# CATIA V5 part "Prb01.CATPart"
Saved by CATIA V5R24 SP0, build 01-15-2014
Part number: Part2
Bounding box of the stored display mesh (mm): x -83 to 0, y -70.837 to 70.837, z -70.764 to 70.764
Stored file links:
  C:\Users\cdl\Downloads\2024_CAD_midterm\Prb02.CATPart
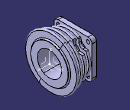
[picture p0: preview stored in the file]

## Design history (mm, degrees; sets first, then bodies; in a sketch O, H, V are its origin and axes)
AxisSystem1: origin (0, 0, 0), X (1, 0, 0), Y (0, 1, 0), Z (0, 0, 1)
Body1 (main body)
  Sketch1 on zx-plane, origin (0, 0, 0), H (-1, 0, 0), V (0, 0, 1)
    construction line L1 (0, 0) -> (74, 0)
    construction line L2 (7, 0) -> (7, 68)
    point P2 (7, 0)
    construction line L3 (22, 0) -> (22, 64)
    point P4 (22, 0)
    construction line L4 (37, 0) -> (37, 60)
    point P6 (37, 0)
    axis line L5 (52, 0) -> (52, 56)
    point P8 (52, 0)
    arc A1 centre (7, 68) radius 3 from (9.9995, 68.0524) to (4.0005, 68.0523) ccw
    arc A2 centre (22, 64) radius 3 from (24.9995, 64.0524) to (19.0005, 64.0523) ccw
    arc A3 centre (37, 60) radius 3 from (39.9995, 60.0524) to (34.0005, 60.0523) ccw
    arc A4 centre (52, 56) radius 3 from (54.9995, 56.0523) to (49.0005, 56.0523) ccw
    line L6 (4.0005, 68.0524) -> (2.8126, 0)
    point P10 (4.0005, 68.0524)
    point P11 (2.8126, 0)
    line L7 (9.9995, 68.0524) -> (11.1874, 0)
    point P13 (11.1874, 0)
    line L8 (19.0005, 64.0524) -> (17.8824, 0)
    point P14 (19.0005, 64.0524)
    point P15 (17.8824, 0)
    line L9 (24.9995, 64.0524) -> (26.1176, 0)
    point P17 (26.1176, 0)
    line L10 (34.0005, 60.0524) -> (32.9522, 0)
    point P18 (34.0005, 60.0524)
    point P19 (32.9522, 0)
    line L11 (39.9995, 60.0524) -> (41.0478, 0)
    point P21 (41.0478, 0)
    line L12 (49.0005, 56.0524) -> (48.0221, 0)
    point P22 (49.0005, 56.0524)
    point P23 (48.0221, 0)
    line L13 (54.9995, 56.0523) -> (55.9779, 0)
    point P25 (55.9779, 0)
    point P26 (4.0005, 68.0523)
    point P27 (19.0005, 64.0523)
    point P28 (34.0005, 60.0523)
    point P29 (49.0005, 56.0523)
    line L14 (2.8126, 0) -> (11.1874, 0)
    line L15 (17.8824, 0) -> (26.1176, 0)
    line L16 (32.9522, 0) -> (41.0478, 0)
    line L17 (48.0221, 0) -> (55.9779, 0)
    distance V L2 = 7
    length L2 = 68
    length L3 = 64
    length L4 = 60
    length L5 = 56
    distance L2 L3 = 15
    distance L3 L4 = 15
    distance L4 L5 = 15
    radius A1 = 3
    radius A2 = 3
    radius A3 = 3
    radius A4 = 3
    angle L6 L7 = 2
    angle L8 L9 = 2
    angle L10 L11 = 2
    angle L12 L13 = 2
    horizontal: L1 H, L14 H, L15 H, L16 H, L17 H
    coincidence: P2 L1, P4 L1, P8 L1, A1 P10, L1 P11, L1 P13, A2 P14, L1 P15, L1 P17, A3 P18, L1 P19, L1 P21, A4 P22, L1 P23, L1 P25, L6 P26, L8 P27, L10 P28, L12 P29
    vertical: L2 V, L3 V, L4 V, L5 V
    midpoint: P6 L1
    tangency: L6 A1, L7 A1, L8 A2, L9 A2, L10 A3, L11 A3, L12 A4, L13 A4
    symmetry: L6 L7 L2, L8 L9 L3, L10 L11 L4, L12 L13 L5
  Shaft1: profile Sketch1, axis Sketch1.H, angle 360
  Sketch2 on zx-plane, origin (0, 0, 0), H (-1, 0, 0), V (0, 0, 1)
    point P1 (7, 0)
    line L1 (7, 0) -> (63, 0)
    line L2 (63, 0) -> (63, 40)
    line L3 (63, 40) -> (7, 40)
    line L4 (7, 40) -> (7, 0)
    distance L4 V = 7
    length L2 = 40
    length L1 = 56
    coincidence: P1 H
    horizontal: L1 H, L3 H
    vertical: L2 V, L4 V
  Shaft2: profile Sketch2, axis axis of face of Shaft1 from Sketch1.L6, angle 360
  Sketch3 on face of Shaft2 from Sketch2.L2, origin (-63, 0, 0), H (0, -1, 0), V (0, 0, 1)
    line L1 (51, 51) -> (51, -51)
    line L2 (51, -51) -> (-51, -51)
    line L3 (-51, -51) -> (-51, 51)
    line L4 (-51, 51) -> (51, 51)
    length L3 = 102
    length L4 = 102
    vertical: L1 V, L3 V
    horizontal: L2 H, L4 H
    equidistance: L1 L3 O, L2 L4 O
  Pad1: profile Sketch3, direction (-1, 0, 0), length 12
  Sketch4 on end face of Pad1, origin (-75, 0, 0), H (0, -1, 0), V (0, 0, 1)
    circle A1 centre (0, 0) radius 39
    radius A1 = 39
  Pad2: profile Sketch4, direction (-1, 0, 0), length 8
  Fillet1: radius 11, on edge [face of Pad1 from Sketch3.L2 | face of Pad1 from Sketch3.L3]; edge [face of Pad1 from Sketch3.L3 | face of Pad1 from Sketch3.L4]; edge [face of Pad1 from Sketch3.L1 | face of Pad1 from Sketch3.L2]; edge [face of Pad1 from Sketch3.L4 | face of Pad1 from Sketch3.L1]
  Sketch5 on zx-plane, origin (0, 0, 0), H (-1, 0, 0), V (0, 0, 1)
    line L1 (7, 36) -> (63, 36)
    line L2 (63, 36) -> (63, 44)
    point P3 (63, 44)
    line L3 (63, 44) -> (7, 59.0052)
    line L4 (7, 59.0052) -> (7, 36)
    reference projected line E1 (63, 51) -> (63, 40) from edge [start face of Pad1 | face of Fillet1]
    distance L4 V = 7
    distance L1 H = 36
    distance P3 H = 44
    angle L1 L3 = 15
    horizontal: L1 H
    vertical: L2 V, L4 V
    coincidence: L2 E1
  Pad3: profile Sketch5, direction (0, 1, 0), length 3, mirrored extent
  CircPattern1: of Pad3, instances 4, angular step 90, axis from end face of Pad2
  Sketch6 on start face of Pad1, origin (-63, 0, 0), H (0, 1, 0), V (0, 0, 1)
    line L1 (40, 30) -> (66.289, 30)
    line L2 (66.289, 30) -> (66.289, 73.0898)
    line L3 (66.289, 73.0898) -> (30, 73.0898)
    line L4 (30, 73.0898) -> (30, 40)
    arc A1 centre (40, 40) radius 10 from (40, 30) to (30, 40) cw
    distance L4 V = 30
    distance H L1 = 30
    radius A1 = 10
    horizontal: L1 H, L3 H
    vertical: L2 V, L4 V
    tangency: A1 L1, A1 L4
  Pocket1: profile Sketch6, direction (1, 0, 0), length 30
  CircPattern2: of Pocket1, instances 4, angular step 90, axis from end face of Pad2
  Sketch7 on zx-plane, origin (0, 0, 0), H (-1, 0, 0), V (0, 0, 1)
    line L1 (0, 0) -> (90, 0)
    line L2 (90, 0) -> (90, 32.5)
    line L3 (90, 32.5) -> (0, 32.5)
    line L4 (0, 32.5) -> (0, 0)
    length L2 = 32.5
    horizontal: L1 H, L3 H
    vertical: L2 V, L4 V
  Groove1: profile Sketch7, axis axis of face of Shaft1 from Sketch1.L6, angle 360
  Sketch8 on zx-plane, origin (0, 0, 0), H (-1, 0, 0), V (0, 0, 1)
    point P1 (0, 50)
    line L1 (0, 50) -> (7, 50)
    line L2 (7, 50) -> (7, 32.5)
    line L3 (7, 32.5) -> (0, 32.5)
    line L4 (0, 32.5) -> (0, 50)
    distance V L2 = 7
    distance L3 H = 32.5
    distance H L1 = 50
    coincidence: P1 V
    horizontal: L1 H, L3 H
    vertical: L2 V, L4 V
  Shaft3: profile Sketch8, axis axis of face of Groove1 from Sketch7.L3, angle 360
  Sketch9 on face of CircPattern2, origin (-63, -33.3512, -38.787), H (0, 1, 0), V (0, 0, 1)
    point P1 (-6.6488, -1.213)
    reference projected line E1 (73.3512, -12.213) -> (-6.6488, -12.213) from edge [face of CircPattern2 | face of Pad1 from Sketch3.L2]
    reference projected line E2 (-17.6488, -1.213) -> (-17.6488, 78.787) from edge [face of CircPattern2 | face of Pad1 from Sketch3.L1]
    distance P1 E1 = 11
    distance P1 E2 = 11
  Hole1: placed by Sketch9, at (-63, -40, -40) direction (-1, 0, 0), diameter 9, depth 12, V-bottom angle 120
  CircPattern3: of Hole1, instances 4, angular step 90, axis from end face of Pad2
  Chamfer1: length 1, angle 45, on edge [face of Pad2 from Sketch4.A1 | end face of Pad2]
  Fillet2: radius 3, on edge [face of Shaft3 from Sketch8.L1 | face of Shaft1 from Sketch1.L6]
